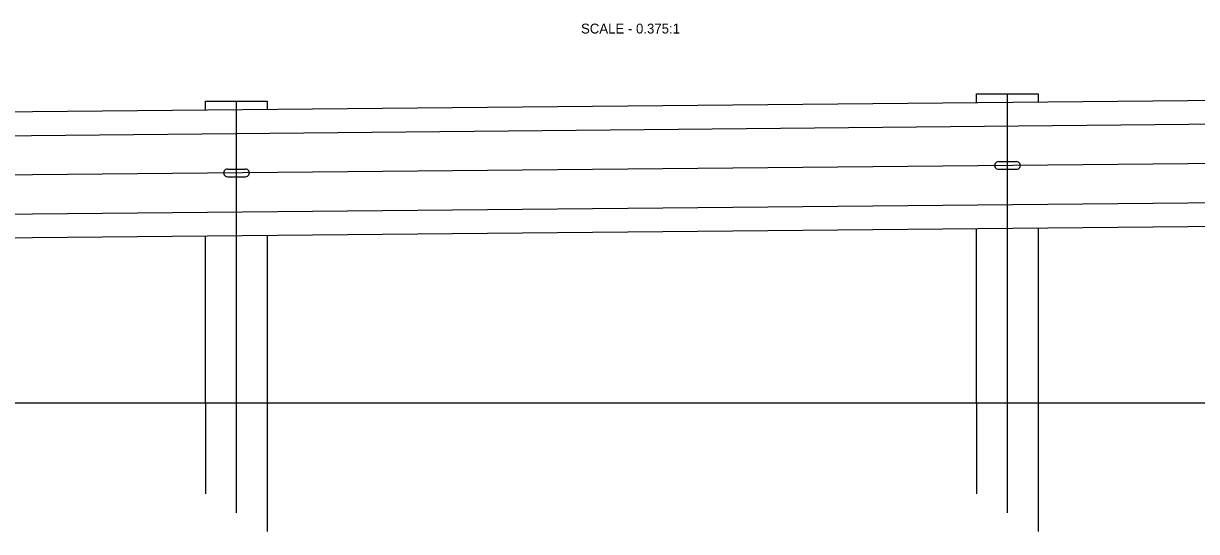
# Model space of a CAD drawing. Extents: x 49991.4 to 50070, y 49987.6 to 50011.4.
# Drawn here: x 50040.78 to 50050.29, y 49991.72 to 49995.84 of the extents above; entities that cross this region are included whole.
import ezdxf

# ---------------------------------------------------------------- set-up
doc = ezdxf.new("R2010")
doc.units = 0
for name, color, linetype in [('Level 1', 7, 'Continuous'), ('Level 2', 7, 'Continuous'), ('Level 4', 7, 'Continuous'), ('Level 5', 7, 'Continuous')]:
    doc.layers.add(name, color=color, linetype=linetype)

msp = doc.modelspace()

# ---------------------------------------------------------------- linework, layer by layer
at = {"layer": 'Level 1'}
for p, q in [((50064.3862, 49995.3494), (50036.2612, 49995.0786)), ((50048.5112, 49995.1965), (50048.5112, 49995.2694)), ((50048.5112, 49995.2694), (50049.0112, 49995.2694)), ((50049.0112, 49995.2694), (50049.0112, 49995.2014)), ((50042.2612, 49995.1364), (50042.2612, 49995.2093)), ((50042.2612, 49995.2093), (50042.7612, 49995.2093)), ((50042.7612, 49995.2093), (50042.7612, 49995.1412)), ((50064.3862, 49995.1567), (50036.2612, 49994.8859)), ((50048.6882, 49994.7206), (50048.8342, 49994.7206)), ((50042.4382, 49994.6605), (50042.5842, 49994.6605)), ((50042.4382, 49994.5982), (50042.5842, 49994.5982)), ((50048.6882, 49994.6584), (50048.8342, 49994.6584)), ((50064.3862, 49994.5212), (50036.2612, 49994.2504)), ((50064.3862, 49994.3285), (50036.2612, 49994.0577)), ((50042.2612, 49992.7661), (50042.2612, 49994.1155)), ((50042.7612, 49994.1203), (50042.7612, 49992.7661)), ((50048.5112, 49992.7661), (50048.5112, 49994.1757)), ((50049.0112, 49994.1805), (50049.0112, 49992.7661)), ((50033.3159, 49992.7661), (50069.9817, 49992.7661))]:
    msp.add_line(p, q, dxfattribs=at)
for centre, start_param, end_param in [((50048.6882, 49994.6895), 4.712389, 7.853982), ((50048.8342, 49994.6895), 1.570796, 4.712389), ((50042.4382, 49994.6293), 4.712389, 7.853982), ((50042.5842, 49994.6293), 1.570796, 4.712389)]:
    msp.add_ellipse(centre, major_axis=(-0.0312, 0), ratio=0.998676, start_param=start_param, end_param=end_param, dxfattribs=at)
at = {"layer": 'Level 4'}
for p, q in [((50042.2612, 49992.7661), (50042.2612, 49992.0279)), ((50042.7612, 49992.7661), (50042.7612, 49991.7239)), ((50048.5112, 49992.7661), (50048.5112, 49992.0277)), ((50049.0112, 49992.7661), (50049.0112, 49991.7237))]:
    msp.add_line(p, q, dxfattribs=at)
at = {"layer": 'Level 5'}
for p, q in [((50048.7612, 49991.8752), (50048.7612, 49995.2694)), ((50042.5112, 49991.8754), (50042.5112, 49995.2093)), ((50064.3862, 49994.839), (50036.2612, 49994.5681))]:
    msp.add_line(p, q, dxfattribs=at)

# ---------------------------------------------------------------- texts
at = {"layer": 'Level 2'}
msp.add_text('SCALE - 0.375:1', height=0.08, dxfattribs=at).set_placement((50045.304, 49995.7583))

doc.saveas('drawing.dxf')
